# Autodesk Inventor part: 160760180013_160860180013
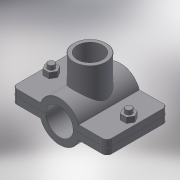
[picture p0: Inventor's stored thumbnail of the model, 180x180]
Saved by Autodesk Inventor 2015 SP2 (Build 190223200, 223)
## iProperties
Created: 2017-05
Part Number: 160760180013_160860180013
Material: Generic
Description: PLASSON SADDLE 180-1.1/4"
Document SubType Name: Modeling
Designer: KIM
Density: 1 g/cm^3
Appearance: Default
Author: KIM
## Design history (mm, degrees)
derived "16076.ipt"
feature "Solid1::16076.ipt"
feature "Solid2::16076.ipt"
tag "TaggingFeature1"
body "Solid1"
other parameters: "d0" = 198, "d1" = 245, "d4" = 154, "d5" = 0, "d6" = 12.25, "d7" = 245, "d8" = 0.1, "d10" = 0, "d11" = 1.8, "d14" = 50.6376, "d20" = 1.8, "d23" = 1.8, "d36" = 15, "d37" = 12, "d38" = 98, "d39" = 0, "d40" = 3, "d41" = 5, "d42" = 0, "d44" = 3, "d45" = 0, "d46" = 1.8, "d51" = 127, "d52" = 38.952, "d53" = 25, "d54" = 0, "d55" = 32, "d57" = 0, "d58" = 194.4, "d60" = 0, "d62" = 15, "d63" = 12, "B_" = 32, "G_" = 38.952, "A_" = 127, "L_" = 245, "L_1" = 154, "l_2" = 25
